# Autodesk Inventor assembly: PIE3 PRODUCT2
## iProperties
Shininess: 64.0
Length Units: 11269
Angle Units: 11279
Time Units: 11290
Mass Units: 11286
Length Display Precision: 3
Angle Display Precision: 2
Compacted: True
Part Number: PIE3 PRODUCT2
Document SubType Name: Assembly
Created: 2004-08
Designer: John Blackburn
Manufacturer: Standard
Standards Organization: Custom
Density: 0.0
Volumn: 0.0
Area: 0.0
PropertySet Name: Model Information
Control State: 0
Master: False
Checked Out: False
Author: John Blackburn
